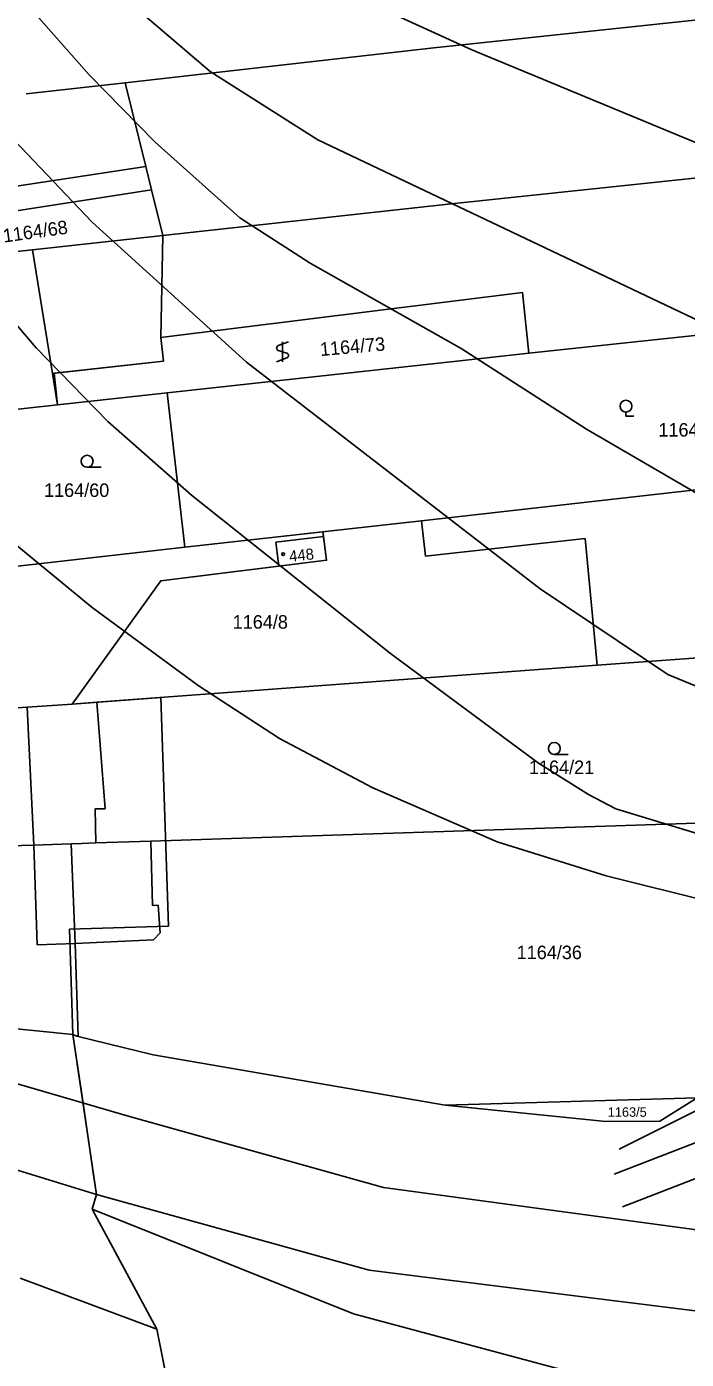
# Model space of a CAD drawing. Extents: x -555860 to -552701, y -1187050 to -1182291.
# Drawn here: x -554278.6 to -554195.5, y -1185298.6 to -1185130.7 of the extents above; entities that cross this region are included whole.
import ezdxf

# ---------------------------------------------------------------- set-up
doc = ezdxf.new("R2010")
doc.units = 0
for name, color, linetype in [('CYKLISTI_stav', 7, 'Continuous'), ('LEG_2b', 7, 'Continuous'), ('Level 25', 7, 'Continuous'), ('Level 32', 7, 'Continuous'), ('Level 40', 7, 'Continuous'), ('Level 41', 7, 'Continuous'), ('navrh_BV', 7, 'Continuous'), ('Poz předměty', 7, 'Continuous')]:
    doc.layers.add(name, color=color, linetype=linetype)

msp = doc.modelspace()

# ---------------------------------------------------------------- linework, layer by layer
at = {"layer": 'CYKLISTI_stav'}
for p, q in [((-554277.67, -1185233.8), (-554278.53, -1185216.41)), ((-554277.67, -1185233.8), (-554277.26, -1185246.39)), ((-554272.48, -1185246.21), (-554272.96, -1185233.64)), ((-554277.26, -1185246.39), (-554272.48, -1185246.21))]:
    msp.add_line(p, q, dxfattribs=at)
at = {"layer": 'Level 25'}
for p, q in [((-554245.59, -1185170.39), (-554246.89, -1185170.86)), ((-554246.34, -1185170.39), (-554246.34, -1185172.89)), ((-554247.09, -1185172.89), (-554245.79, -1185172.4)), ((-554246.89, -1185171.47), (-554245.79, -1185171.8)), ((-554203.07, -1185179.24), (-554203.07, -1185179.74)), ((-554203.07, -1185179.74), (-554202.07, -1185179.74)), ((-554270.96, -1185186.18), (-554269.21, -1185186.18)), ((-554212.1, -1185222.38), (-554210.35, -1185222.38))]:
    msp.add_line(p, q, dxfattribs=at)
for centre, radius in [((-554203.07, -1185178.49), 0.75), ((-554270.96, -1185185.43), 0.75), ((-554246.27, -1185197.14), 0.175), ((-554212.1, -1185221.63), 0.75)]:
    msp.add_circle(centre, radius, dxfattribs=at)
for centre, start, end in [((-554246.76, -1185171.17), 113.579, 246.421), ((-554245.92, -1185172.1), 293.574, 66.426)]:
    msp.add_arc(centre, 0.329, start, end, dxfattribs=at)
at = {"layer": 'Level 32'}
for points in [[(-554278.63, -1185139.14), (-554266.16, -1185137.73), (-554263.56, -1185148.28), (-554262.83, -1185151.21), (-554261.41, -1185156.97), (-554261.68, -1185169.84)], [(-554261.68, -1185169.84), (-554261.34, -1185172.83), (-554275.12, -1185174.33), (-554274.69, -1185178.31), (-554260.88, -1185176.8), (-554258.65, -1185196.28), (-554241.26, -1185194.32), (-554240.79, -1185197.9), (-554261.68, -1185200.5), (-554272.84, -1185216.03), (-554261.67, -1185215.2), (-554260.7, -1185244.02), (-554273.19, -1185244.42), (-554272.75, -1185257.67), (-554269.79, -1185277.83), (-554270.32, -1185279.7), (-554262.17, -1185294.82), (-554258.28, -1185314.32)]]:
    msp.add_lwpolyline(points, dxfattribs=at)
at = {"layer": 'Level 40'}
msp.add_lwpolyline([(-554285.7, -1185161.43), (-554277.38, -1185171.13), (-554268.36, -1185180.42), (-554257.83, -1185189.71), (-554232.73, -1185209.68), (-554214.07, -1185223.48), (-554207.77, -1185227.43), (-554204.33, -1185229.25), (-554190.64, -1185233.38)], dxfattribs=at)
at = {"layer": 'Level 41'}
for points in [[(-554264.07, -1185128.98), (-554255.47, -1185136.33), (-554241.88, -1185144.93), (-554181.15, -1185173.77), (-554175.16, -1185176.85), (-554165.62, -1185180.28), (-554150.09, -1185185.55), (-554140.38, -1185187.77), (-554131.31, -1185188.9), (-554124.3, -1185189.44), (-554115.96, -1185188.73), (-554110.44, -1185188.46), (-554105.44, -1185187.22), (-554099.76, -1185184.17), (-554096.43, -1185180.42), (-554093.1, -1185175.29), (-554092.13, -1185170.86), (-554092.36, -1185166.79), (-554093.1, -1185161.98), (-554095.6, -1185155.32), (-554104.89, -1185137.58), (-554120.7, -1185110.96)], [(-554129.43, -1185113.18), (-554117.09, -1185135.36), (-554111.41, -1185146.73), (-554109.88, -1185153.38), (-554109.6, -1185157.82), (-554110.19, -1185161.51), (-554111.27, -1185163.64), (-554112.99, -1185165.47), (-554114.73, -1185166.97), (-554118.11, -1185168.6), (-554122.08, -1185169.61), (-554127.91, -1185170.02), (-554135.67, -1185169.33), (-554146.62, -1185167.45), (-554153.14, -1185165.86), (-554160.31, -1185162.99), (-554167.84, -1185159.21), (-554189.75, -1185147.15), (-554222.47, -1185133.56), (-554238, -1185126.49)], [(-554187.53, -1185193.32), (-554208.05, -1185181.39), (-554223.84, -1185171.24), (-554242.85, -1185160.46), (-554251.73, -1185154.77), (-554262.4, -1185145.2), (-554270.72, -1185136.75), (-554282.79, -1185123.02)], [(-554070.5, -1185122.88), (-554062.04, -1185146.18), (-554052.48, -1185169.47), (-554048.18, -1185182.78), (-554047.34, -1185187.77), (-554047.15, -1185191.87), (-554047.48, -1185193.87), (-554048.31, -1185196.82), (-554050.95, -1185201.36), (-554053.5, -1185203.42), (-554058.16, -1185206.21), (-554073.83, -1185213.84), (-554087.7, -1185219.8), (-554118.06, -1185238.94), (-554131.65, -1185246.28), (-554142.88, -1185251.14), (-554157.72, -1185254.05), (-554182.96, -1185261.63), (-554203.91, -1185272.11)], [(-554204.55, -1185275.3), (-554175.78, -1185264.15), (-554160.95, -1185260.3), (-554131.51, -1185254.19), (-554116.26, -1185250.03), (-554101.28, -1185244.76), (-554096.78, -1185242.12), (-554087.14, -1185235.47), (-554072.3, -1185221.88), (-554055.8, -1185211.76), (-554047.21, -1185205.1), (-554045.37, -1185202.59), (-554042.57, -1185197.48), (-554041.24, -1185193.87), (-554040.59, -1185190.88), (-554040.55, -1185187.77), (-554040.75, -1185183.29), (-554041.52, -1185178.62), (-554050.26, -1185148.12), (-554053.17, -1185135.91), (-554053.72, -1185124.54)], [(-554289.99, -1185134.67), (-554270.31, -1185155.32), (-554250.89, -1185172.94), (-554213.87, -1185201.5), (-554197.79, -1185212.31), (-554190.64, -1185215.23)], [(-554028.71, -1185137.09), (-554031.68, -1185137.44), (-554034.15, -1185138.08), (-554037.29, -1185141.54), (-554038.89, -1185144.65), (-554039.17, -1185150.61), (-554037.78, -1185158.93), (-554031.68, -1185182.23), (-554031.35, -1185187.74), (-554031.54, -1185194.15), (-554032.23, -1185196.65), (-554033.99, -1185200.28), (-554035.84, -1185203.16), (-554063.01, -1185231.73), (-554069.67, -1185237.83), (-554076.88, -1185243.09), (-554089.91, -1185248.5), (-554102.56, -1185252.68), (-554129.76, -1185260), (-554148.06, -1185262.35), (-554164.98, -1185265.54), (-554187.46, -1185273.16), (-554203.52, -1185279.38)], [(-554288.61, -1185188.88), (-554270.31, -1185203.86), (-554256.99, -1185213.7), (-554246.73, -1185220.36), (-554234.95, -1185226.59), (-554219.28, -1185233.39), (-554205.55, -1185237.69), (-554192.24, -1185241.02)]]:
    msp.add_lwpolyline(points, dxfattribs=at)
at = {"layer": 'navrh_BV'}
for p, q in [((-554227.29, -1185133.34), (-554142.52, -1185124.33)), ((-554266.16, -1185137.73), (-554227.29, -1185133.34)), ((-554278.63, -1185139.14), (-554266.16, -1185137.73)), ((-554266.16, -1185137.73), (-554263.56, -1185148.28)), ((-554118.86, -1185141.78), (-554225.47, -1185153.04)), ((-554263.56, -1185148.28), (-554303.16, -1185154.3)), ((-554263.56, -1185148.28), (-554262.83, -1185151.21)), ((-554262.83, -1185151.21), (-554292.19, -1185155.76)), ((-554262.83, -1185151.21), (-554261.41, -1185156.97)), ((-554261.41, -1185156.97), (-554225.47, -1185153.04)), ((-554277.83, -1185158.77), (-554261.41, -1185156.97)), ((-554291.77, -1185160.3), (-554277.83, -1185158.77)), ((-554277.83, -1185158.77), (-554275.32, -1185174.36)), ((-554215.29, -1185171.83), (-554110.95, -1185160.56)), ((-554261.68, -1185169.84), (-554216.11, -1185164.18)), ((-554216.11, -1185164.18), (-554215.29, -1185171.83)), ((-554261.34, -1185172.83), (-554261.68, -1185169.84)), ((-554260.88, -1185176.8), (-554223.64, -1185172.74)), ((-554223.64, -1185172.74), (-554215.29, -1185171.83)), ((-554275.32, -1185174.36), (-554261.34, -1185172.83)), ((-554275.32, -1185174.36), (-554274.69, -1185178.31)), ((-554274.69, -1185178.31), (-554260.88, -1185176.8)), ((-554260.88, -1185176.8), (-554258.65, -1185196.28)), ((-554282.39, -1185179.15), (-554274.69, -1185178.31)), ((-554228.84, -1185192.93), (-554157.9, -1185184.97)), ((-554258.65, -1185196.28), (-554228.84, -1185192.93)), ((-554228.84, -1185192.93), (-554228.34, -1185197.41)), ((-554280.06, -1185198.68), (-554258.65, -1185196.28)), ((-554247.2, -1185195.65), (-554241.18, -1185194.9)), ((-554246.81, -1185198.65), (-554247.2, -1185195.65)), ((-554241.18, -1185194.9), (-554240.79, -1185197.9)), ((-554228.34, -1185197.41), (-554208.21, -1185195.15)), ((-554208.21, -1185195.15), (-554206.71, -1185211.14)), ((-554240.79, -1185197.9), (-554246.81, -1185198.65)), ((-554155.2, -1185207.34), (-554206.71, -1185211.14)), ((-554206.71, -1185211.14), (-554269.74, -1185215.8)), ((-554278.53, -1185216.41), (-554284.17, -1185216.78)), ((-554272.84, -1185216.03), (-554278.53, -1185216.41)), ((-554269.74, -1185215.8), (-554272.84, -1185216.03)), ((-554268.67, -1185229.23), (-554269.74, -1185215.8)), ((-554269.94, -1185229.25), (-554268.67, -1185229.23)), ((-554269.85, -1185233.54), (-554269.94, -1185229.25)), ((-554262.94, -1185233.31), (-554152.51, -1185229.7)), ((-554317.32, -1185235.1), (-554277.67, -1185233.8)), ((-554277.67, -1185233.8), (-554272.96, -1185233.64)), ((-554272.96, -1185233.64), (-554271.67, -1185233.6)), ((-554271.67, -1185233.6), (-554269.85, -1185233.54)), ((-554269.85, -1185233.54), (-554262.94, -1185233.31)), ((-554262.74, -1185241.43), (-554262.94, -1185233.31)), ((-554261.99, -1185241.38), (-554262.74, -1185241.43)), ((-554261.77, -1185244.88), (-554261.99, -1185241.38)), ((-554262.6, -1185245.74), (-554261.77, -1185244.88)), ((-554272.48, -1185246.21), (-554262.6, -1185245.74)), ((-554272.08, -1185257.92), (-554272.48, -1185246.21)), ((-554265.9, -1185267.95), (-554310.65, -1185254.89)), ((-554287.74, -1185256.16), (-554272.75, -1185257.67)), ((-554272.75, -1185257.67), (-554272.24, -1185257.88)), ((-554272.24, -1185257.88), (-554272.08, -1185257.92)), ((-554272.08, -1185257.92), (-554262.63, -1185260.23)), ((-554262.63, -1185260.23), (-554225.84, -1185266.59)), ((-554311.45, -1185265.09), (-554269.79, -1185277.83)), ((-554225.84, -1185266.59), (-554194.09, -1185265.67)), ((-554205.6, -1185268.64), (-554225.84, -1185266.59)), ((-554194.09, -1185265.67), (-554198.8, -1185268.6)), ((-554233.6, -1185276.98), (-554265.9, -1185267.95)), ((-554198.8, -1185268.6), (-554205.6, -1185268.64)), ((-554269.79, -1185277.83), (-554270.32, -1185279.7)), ((-554269.79, -1185277.83), (-554235.43, -1185287.38)), ((-554178.81, -1185284.35), (-554233.6, -1185276.98)), ((-554270.32, -1185279.7), (-554237.4, -1185292.88)), ((-554279.39, -1185288.38), (-554262.17, -1185294.82)), ((-554235.43, -1185287.38), (-554179.88, -1185294.33)), ((-554237.4, -1185292.88), (-554199.59, -1185303)), ((-554262.17, -1185294.82), (-554258.28, -1185314.32))]:
    msp.add_line(p, q, dxfattribs=at)
at = {"layer": 'Poz předměty'}
for points in [[(-554261.41, -1185156.97), (-554261.68, -1185169.84)], [(-554241.18, -1185194.9), (-554241.26, -1185194.32)], [(-554246.81, -1185198.65), (-554261.68, -1185200.5), (-554272.84, -1185216.03)], [(-554261.67, -1185215.2), (-554260.7, -1185244.02)], [(-554272.75, -1185257.67), (-554271.48, -1185266.32), (-554270.19, -1185275.1), (-554269.79, -1185277.83)], [(-554270.32, -1185279.7), (-554262.17, -1185294.82)]]:
    msp.add_lwpolyline(points, dxfattribs=at)

# ---------------------------------------------------------------- texts
at = {"layer": 'LEG_2b'}
for s, height, rotation, p in [('1164/68', 1.7, 8, (-554281.45, -1185157.88)), ('1164/73', 1.7, 5, (-554241.54, -1185172.18)), ('448', 1.4, 6, (-554245.43, -1185198.11))]:
    msp.add_text(s, height=height, rotation=rotation, dxfattribs=at).set_placement(p)
for s, height, p in [('1164/7', 1.7, (-554198.98, -1185182.32)), ('1164/60', 1.7, (-554276.39, -1185189.93)), ('1164/8', 1.7, (-554252.62, -1185206.53)), ('1164/21', 1.7, (-554215.29, -1185224.85)), ('1164/36', 1.7, (-554216.84, -1185248.18)), ('1163/5', 1.2, (-554205.36, -1185268.05))]:
    msp.add_text(s, height=height, dxfattribs=at).set_placement(p)

doc.saveas('drawing.dxf')
